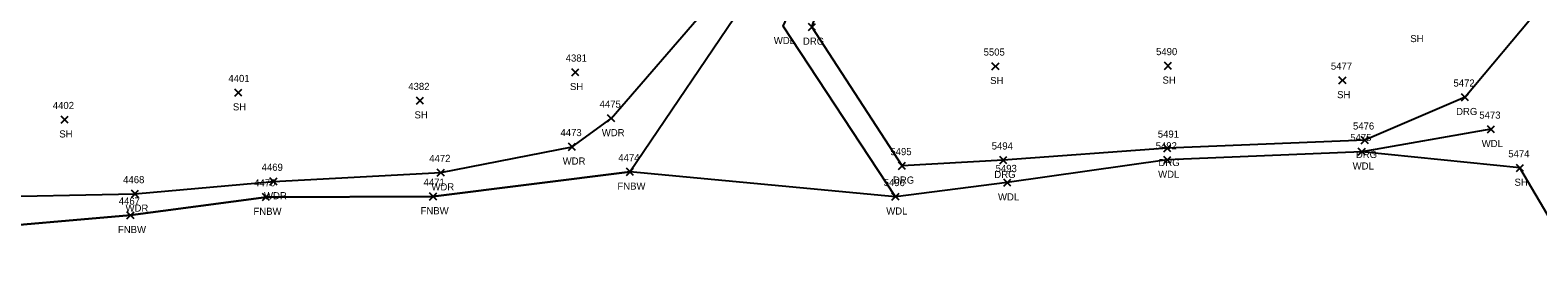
# Model space of a CAD drawing. Extents: x 1472233 to 1475777, y 540726 to 543442.
# Drawn here: x 1474285.9 to 1474709.1, y 541290.4 to 541355.8 of the extents above; entities that cross this region are included whole.
import ezdxf

# ---------------------------------------------------------------- set-up
doc = ezdxf.new("R2010")
doc.units = 0
for name, color, linetype in [('L_A', 7, 'Continuous'), ('L_I', 7, 'Continuous'), ('L_TIC', 7, 'Continuous'), ('LAWA', 7, 'Continuous'), ('LFNC', 7, 'Continuous'), ('LSOGP', 7, 'Continuous'), ('R_A', 7, 'Continuous'), ('R_I', 7, 'Continuous'), ('R_TIC', 7, 'Continuous'), ('RDG', 7, 'Continuous')]:
    doc.layers.add(name, color=color, linetype=linetype)

msp = doc.modelspace()

# ---------------------------------------------------------------- linework, layer by layer
at = {"layer": 'L_TIC'}
for points in [[(1474555.89, 541344.67), (1474557.89, 541346.67)], [(1474557.89, 541344.67), (1474555.89, 541346.67)], [(1474604.29, 541344.79), (1474606.29, 541346.79)], [(1474606.29, 541344.79), (1474604.29, 541346.79)], [(1474437.95, 541342.98), (1474439.95, 541344.98)], [(1474439.95, 541342.98), (1474437.95, 541344.98)], [(1474653.28, 541340.7), (1474655.28, 541342.7)], [(1474655.28, 541340.7), (1474653.28, 541342.7)], [(1474343.35, 541337.26), (1474345.35, 541339.26)], [(1474345.35, 541337.26), (1474343.35, 541339.26)], [(1474394.32, 541335.01), (1474396.32, 541337.01)], [(1474396.32, 541335.01), (1474394.32, 541337.01)], [(1474294.62, 541329.65), (1474296.62, 541331.65)], [(1474296.62, 541329.65), (1474294.62, 541331.65)], [(1474448.02, 541330.01), (1474450.02, 541332.01)], [(1474450.02, 541330.01), (1474448.02, 541332.01)], [(1474694.95, 541326.94), (1474696.95, 541328.94)], [(1474696.95, 541326.94), (1474694.95, 541328.94)], [(1474437.04, 541322.03), (1474439.04, 541324.03)], [(1474439.04, 541322.03), (1474437.04, 541324.03)], [(1474604.11, 541318.32), (1474606.11, 541320.32)], [(1474606.11, 541318.32), (1474604.11, 541320.32)], [(1474658.72, 541320.64), (1474660.72, 541322.64)], [(1474660.72, 541320.64), (1474658.72, 541322.64)], [(1474400.2, 541314.77), (1474402.2, 541316.77)], [(1474402.2, 541314.77), (1474400.2, 541316.77)], [(1474453.29, 541314.99), (1474455.29, 541316.99)], [(1474455.29, 541314.99), (1474453.29, 541316.99)], [(1474703.08, 541316.07), (1474705.08, 541318.07)], [(1474705.08, 541316.07), (1474703.08, 541318.07)], [(1474353.21, 541312.28), (1474355.21, 541314.28)], [(1474355.21, 541312.28), (1474353.21, 541314.28)], [(1474559.18, 541311.95), (1474561.18, 541313.95)], [(1474561.18, 541311.95), (1474559.18, 541313.95)], [(1474314.34, 541308.8), (1474316.34, 541310.8)], [(1474316.34, 541308.8), (1474314.34, 541310.8)], [(1474351.14, 541307.9), (1474353.14, 541309.9)], [(1474353.14, 541307.9), (1474351.14, 541309.9)], [(1474398.05, 541308.06), (1474400.05, 541310.06)], [(1474400.05, 541308.06), (1474398.05, 541310.06)], [(1474527.8, 541307.98), (1474529.8, 541309.98)], [(1474529.8, 541307.98), (1474527.8, 541309.98)], [(1474313.1, 541302.78), (1474315.1, 541304.78)], [(1474315.1, 541302.78), (1474313.1, 541304.78)]]:
    msp.add_lwpolyline(points, dxfattribs=at)
at = {"layer": 'LAWA'}
for points in [[(1474695.95, 541327.94), (1474659.72, 541321.64), (1474605.11, 541319.32), (1474560.18, 541312.95), (1474528.8, 541308.98), (1474497.25, 541356.92), (1474505.52, 541374.97), (1474525.17, 541396.98), (1474538.81, 541416.3)], [(1474001.22, 541297.39), (1474044.64, 541302.67), (1474096, 541301.72), (1474147.95, 541302.09), (1474184.44, 541304.63), (1474224.1, 541307.12), (1474269.42, 541308.87), (1474315.34, 541309.8), (1474354.21, 541313.28), (1474401.2, 541315.77), (1474438.04, 541323.03), (1474449.02, 541331.01), (1474476.08, 541362.25)]]:
    msp.add_lwpolyline(points, dxfattribs=at)
at = {"layer": 'LFNC'}
msp.add_lwpolyline([(1474093.5, 541290.39), (1474146.46, 541292.93), (1474183.3, 541296.48), (1474218.55, 541296.06), (1474266.73, 541299.66), (1474314.1, 541303.78), (1474352.14, 541308.9), (1474399.05, 541309.06), (1474454.29, 541315.99), (1474487.49, 541365.16)], dxfattribs=at)
at = {"layer": 'LSOGP'}
msp.add_lwpolyline([(1474714.13, 541299.97), (1474704.08, 541317.07), (1474659.72, 541321.64), (1474605.11, 541319.32), (1474560.18, 541312.95), (1474528.8, 541308.98), (1474454.29, 541315.99), (1474399.05, 541309.06), (1474352.14, 541308.9), (1474314.1, 541303.78), (1474266.73, 541299.66)], dxfattribs=at)
at = {"layer": 'R_TIC'}
for points in [[(1474504.35, 541355.73), (1474506.35, 541357.73)], [(1474506.35, 541355.73), (1474504.35, 541357.73)], [(1474687.69, 541335.96), (1474689.69, 541337.96)], [(1474689.69, 541335.96), (1474687.69, 541337.96)], [(1474659.55, 541323.88), (1474661.55, 541325.88)], [(1474661.55, 541323.88), (1474659.55, 541325.88)], [(1474558.08, 541318.27), (1474560.08, 541320.27)], [(1474560.08, 541318.27), (1474558.08, 541320.27)], [(1474604.14, 541321.61), (1474606.14, 541323.61)], [(1474606.14, 541321.61), (1474604.14, 541323.61)], [(1474529.64, 541316.68), (1474531.64, 541318.68)], [(1474531.64, 541316.68), (1474529.64, 541318.68)]]:
    msp.add_lwpolyline(points, dxfattribs=at)
at = {"layer": 'RDG'}
msp.add_lwpolyline([(1474771.15, 541451.97), (1474774.94, 541432.6), (1474736.77, 541389.66), (1474709.58, 541361.92), (1474688.69, 541336.96), (1474660.55, 541324.88), (1474605.14, 541322.61), (1474559.08, 541319.27), (1474530.64, 541317.68), (1474505.35, 541356.73), (1474510.5, 541370.9), (1474529.64, 541392.89), (1474545.34, 541414.19), (1474568.38, 541444.04), (1474582.3, 541429.97)], dxfattribs=at)

# ---------------------------------------------------------------- texts
at = {"layer": 'L_A'}
for s, p in [('SH', (1474673.32, 541352.46)), ('WDL', (1474494.66, 541351.92)), ('SH', (1474555.38, 541340.67)), ('SH', (1474603.78, 541340.79)), ('SH', (1474437.44, 541338.98)), ('SH', (1474652.77, 541336.7)), ('SH', (1474342.83, 541333.26)), ('SH', (1474393.81, 541331.01)), ('SH', (1474294.11, 541325.65)), ('WDR', (1474446.38, 541326.01)), ('WDL', (1474693.36, 541322.94)), ('WDR', (1474435.4, 541318.03)), ('WDL', (1474602.53, 541314.32)), ('WDL', (1474657.14, 541316.64)), ('WDR', (1474398.56, 541310.77)), ('FNBW', (1474450.76, 541310.99)), ('SH', (1474702.57, 541312.07)), ('WDR', (1474351.57, 541308.28)), ('WDL', (1474557.59, 541307.95)), ('WDR', (1474312.7, 541304.8)), ('FNBW', (1474348.61, 541303.9)), ('FNBW', (1474395.52, 541304.06)), ('WDL', (1474526.22, 541303.98)), ('FNBW', (1474310.57, 541298.78))]:
    msp.add_text(s, height=2, dxfattribs=at).set_placement(p)
at = {"layer": 'L_I'}
for s, p in [('5505', (1474553.55, 541348.67)), ('5490', (1474601.95, 541348.79)), ('4381', (1474436.25, 541346.98)), ('5477', (1474651.02, 541344.7)), ('4401', (1474341.57, 541341.26)), ('4382', (1474392.06, 541339.01)), ('4402', (1474292.28, 541333.65)), ('4475', (1474445.76, 541334.01)), ('5473', (1474692.69, 541330.94)), ('4473', (1474434.78, 541326.03)), ('5475', (1474656.46, 541324.64)), ('4472', (1474397.94, 541318.77)), ('4474', (1474451.03, 541318.99)), ('5492', (1474601.85, 541322.32)), ('5474', (1474700.82, 541320.07)), ('4469', (1474350.9, 541316.28)), ('5493', (1474556.92, 541315.95)), ('4468', (1474312.03, 541312.8)), ('4470', (1474348.8, 541311.9)), ('4471', (1474396.36, 541312.06)), ('5496', (1474525.49, 541311.98)), ('4467', (1474310.79, 541306.78))]:
    msp.add_text(s, height=2, dxfattribs=at).set_placement(p)
at = {"layer": 'R_A'}
for p in [(1474502.84, 541351.73), (1474686.18, 541331.96), (1474658.04, 541319.88), (1474556.57, 541314.27), (1474602.63, 541317.61), (1474528.12, 541312.68)]:
    msp.add_text('DRG', height=2, dxfattribs=at).set_placement(p)
at = {"layer": 'R_I'}
for s, p in [('5472', (1474685.43, 541339.96)), ('5476', (1474657.23, 541327.88)), ('5491', (1474602.44, 541325.61)), ('5495', (1474527.38, 541320.68)), ('5494', (1474555.82, 541322.27))]:
    msp.add_text(s, height=2, dxfattribs=at).set_placement(p)

doc.saveas('drawing.dxf')
